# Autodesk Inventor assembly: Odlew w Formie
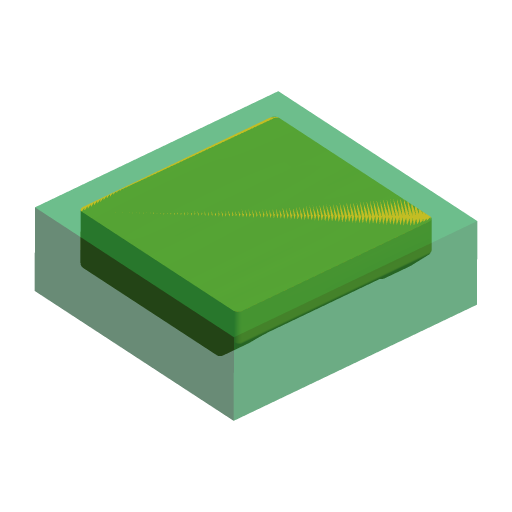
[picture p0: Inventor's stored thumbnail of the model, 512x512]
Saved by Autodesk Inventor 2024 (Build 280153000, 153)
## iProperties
Created: 2023-03
Part Number: Odlew w Formie
Document SubType Name: Assembly
Designer: Andrzej Jaskulski
Checked By: A.J.
Engr Approved By: Andrzej Jaskulski
Mfg Approved By: Andrzej Jaskulski
Authority: A.J.
Company: ATC
Control State: 0
Master: False
Checked Out: False
Shininess: 20.0
Length Units: 11269
Angle Units: 11279
Time Units: 11290
Mass Units: 11283
Length Display Precision: 3
Angle Display Precision: 2
Compacted: True
Density: 0.0
Volumn: 0.0
Area: 0.0
PropertySet Name: Model Information
Title: A.J.: Kurs R2024-MEP
Author: Andrzej Jaskulski
Revision Number: 1/24
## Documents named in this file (3)
- C:\Users\AndJas\Documents\R2024-MEP\Obszar roboczy\Odlew w Formie.iam
- C:\Users\AndJas\Documents\R2024-MEP\Obszar roboczy\Odlew Surowy.ipt
- C:\Users\AndJas\Documents\R2024-MEP\Obszar roboczy\Forma.ipt
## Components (2 placed, 2 different names)
1. Forma:1 — Równoległe:1, Równoległe:2, Równoległe:3, Równoległe:4, Równoległe:5, Równoległe:6
2. Odlew Surowy:1 — Równoległe:1, Równoległe:2, Równoległe:3, Równoległe:4, Równoległe:5, Równoległe:6
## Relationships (6: Flush 6)
- Równoległe:1 [Flush]: Forma:1 ↔ Odlew Surowy:1
- Równoległe:2 [Flush]: Forma:1 ↔ Odlew Surowy:1
- Równoległe:3 [Flush]: Forma:1 ↔ Odlew Surowy:1
- Równoległe:4 [Flush]: Forma:1 ↔ Odlew Surowy:1
- Równoległe:5 [Flush]: Forma:1 ↔ Odlew Surowy:1
- Równoległe:6 [Flush]: Forma:1 ↔ Odlew Surowy:1
## Named parameters: SZEROKOŚĆ = 85 mm, NADDATEK = 3 mm, PROMIEŃ = 2 mm
